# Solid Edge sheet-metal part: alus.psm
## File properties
Last saved by: Georg
Revision: 69
Accuracy: 0,990
Material Thickness: 50,00 mm
Bend Radius: 1,00 mm
Relief Width: 1,00 mm
Relief Length: 0,00 mm
Neutral Factor: 0,330
Minimum Arc Length: 0,10 mm
Deviational Tolerance: 0,10 mm
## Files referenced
!C:\Users\Georg\Desktop\lennuk.asm
..\lennuk.asm
C:\Users\Georg\Desktop\alus.psm
C:\Users\Georg\Desktop\kere.par
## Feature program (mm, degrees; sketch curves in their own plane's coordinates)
base tab "unnamed BaseTab 1"
flange "Flange_3"
flange "Flange_4"
flange "Flange_5"
flange "Flange_6"
sketch for "ExtrudedCutout_2" plane through (0, 2753.887, -447.5635) normal (0, -1, 0) x-axis (1, 0, 0)
extrude "ExtrudedCutout_2" cut
louver "Louver_2"  LouverDepth = 122.0175 mm; LouverHeight = 62.1197 mm
dimple "Dimple_1"
drawn cutout "DrawnCutout_1"
gusset "Gusset_1"  Offset_From_Bend = 199.4548 mm
bead "unnamed Bead 1"
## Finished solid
Body 1: solid body, 81 faces, 206 edges, 126 vertices.
  Faces by surface: plane 43, cylinder 20, torus 9, cone 4, sphere 4, swept 1
  Edges by curve: line 122, circle 72, intersection 9, ellipse 2, spline 1
Bounding box of the edges (mm; curved faces can reach further): 1118.215 x 3738.019 x 931.256, from (-559.1076, 1340.0506, -1353.8194) to (559.1076, 5078.0691, -422.5635).
Cylindrical faces by radius (mm): R1 x5, R50 x4, R51 x5, R100.8951 x1, R138.0185 x1, R150.8951 x1, R188.0185 x1, R302.0325 x1, R352.0325 x1
Conical faces (half-angle, radius in mm at the cone's reference point): 15 deg R15.0701 x1, 15 deg R31.8169 x1, 15 deg R63.3663 x1, 15 deg R80.1132 x1
Toroidal faces (ring radius, tube radius in mm): R25 r50 x2, R80.1132 r50 x2, R138.0185 r50 x1, R188.0185 r50 x1, R353.0325 r1 x2, R353.0325 r51 x1
Spherical faces by radius (mm): R100.8951 x2, R150.8951 x2
Planar faces by outward normal: +x 6, +y 4, +z 8, -x 6, -y 3, -z 8, oblique 8
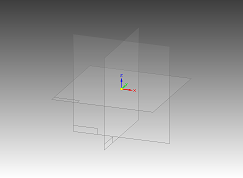
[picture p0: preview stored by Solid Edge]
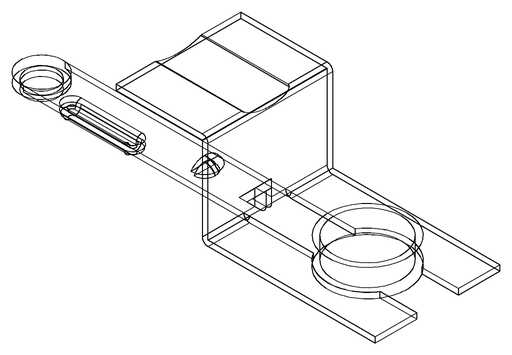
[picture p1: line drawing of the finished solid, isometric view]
